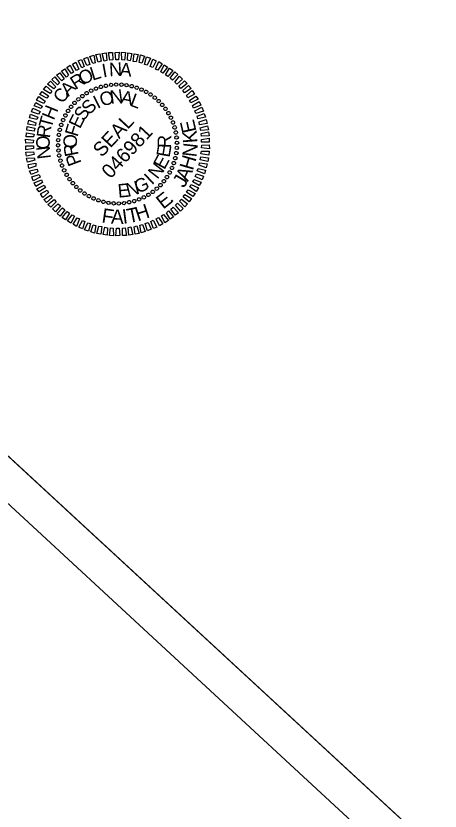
# Model space of a CAD drawing. Extents: x 1768274 to 1769121, y 999922 to 1000687.
# Drawn here: x 1769004.6 to 1769037.2, y 1000252.8 to 1000314 of the extents above; entities that cross this region are included whole.
import ezdxf

# ---------------------------------------------------------------- set-up
doc = ezdxf.new("R2010")
doc.units = 0
for name, color, linetype in [('E_NCDOT_Terrain_Model_Contour_Major', 7, 'Continuous'), ('E_NCDOT_Terrain_Model_Spot_Elevation', 7, 'Continuous'), ('E_NCDOT_Terrain_Model_Triangle_Vertices', 7, 'Continuous'), ('E_NCDOT_Terrain_Model_Void', 7, 'Continuous')]:
    doc.layers.add(name, color=color, linetype=linetype)

msp = doc.modelspace()

# ---------------------------------------------------------------- linework, layer by layer
at = {"layer": 'E_NCDOT_Terrain_Model_Contour_Major'}
msp.add_line((1769116.231, 1000172.715), (1768961.29, 1000315.942), dxfattribs=at)
at = {"layer": 'E_NCDOT_Terrain_Model_Spot_Elevation'}
msp.add_lwpolyline([(1768729.032, 1000071.305), (1768959.819, 1000320.98), (1769121.372, 1000171.648), (1768890.585, 999921.973)], close=True, dxfattribs=at)
at = {"layer": 'E_NCDOT_Terrain_Model_Triangle_Vertices'}
msp.add_line((1769121.372, 1000171.648), (1768959.819, 1000320.98), dxfattribs=at)
at = {"layer": 'E_NCDOT_Terrain_Model_Void'}
for p, q in [((1769010.398, 1000308.223), (1769010.398, 1000308.223)), ((1769010.766, 1000308.38), (1769010.766, 1000308.38)), ((1769011.141, 1000308.517), (1769011.141, 1000308.517)), ((1769011.531, 1000308.603), (1769011.531, 1000308.603)), ((1769011.928, 1000308.67), (1769011.928, 1000308.67)), ((1769012.32, 1000308.692), (1769012.32, 1000308.692)), ((1769012.727, 1000308.689), (1769012.727, 1000308.689)), ((1769013.116, 1000308.64), (1769013.116, 1000308.64)), ((1769013.512, 1000308.558), (1769013.512, 1000308.558)), ((1769013.897, 1000308.451), (1769013.897, 1000308.451)), ((1769014.264, 1000308.311), (1769014.264, 1000308.311)), ((1769009.724, 1000307.803), (1769009.724, 1000307.803)), ((1769010.044, 1000308.029), (1769010.044, 1000308.029)), ((1769014.619, 1000308.131), (1769014.619, 1000308.131)), ((1769014.963, 1000307.913), (1769014.963, 1000307.913)), ((1769015.288, 1000307.687), (1769015.288, 1000307.687)), ((1769008.853, 1000306.982), (1769008.853, 1000306.982)), ((1769009.119, 1000307.283), (1769009.119, 1000307.283)), ((1769009.411, 1000307.559), (1769009.411, 1000307.559)), ((1769015.588, 1000307.421), (1769015.588, 1000307.421)), ((1769015.864, 1000307.129), (1769015.864, 1000307.129)), ((1769008.628, 1000306.657), (1769008.628, 1000306.657)), ((1769016.109, 1000306.816), (1769016.109, 1000306.816)), ((1769016.334, 1000306.496), (1769016.334, 1000306.496)), ((1769008.229, 1000305.958), (1769008.229, 1000305.958)), ((1769008.409, 1000306.313), (1769008.409, 1000306.313)), ((1769016.529, 1000306.143), (1769016.529, 1000306.143)), ((1769016.685, 1000305.775), (1769016.685, 1000305.775)), ((1769007.982, 1000305.207), (1769007.982, 1000305.207)), ((1769008.089, 1000305.591), (1769008.089, 1000305.591)), ((1769016.822, 1000305.4), (1769016.822, 1000305.4)), ((1769007.901, 1000304.81), (1769007.901, 1000304.81)), ((1769016.909, 1000305.009), (1769016.909, 1000305.009)), ((1769016.976, 1000304.612), (1769016.976, 1000304.612)), ((1769007.848, 1000304.015), (1769007.848, 1000304.015)), ((1769007.851, 1000304.421), (1769007.851, 1000304.421)), ((1769012.423, 1000304.117), (1769012.423, 1000304.117)), ((1769016.998, 1000304.22), (1769016.998, 1000304.22)), ((1769007.87, 1000303.622), (1769007.87, 1000303.622)), ((1769016.945, 1000303.424), (1769016.945, 1000303.424)), ((1769016.994, 1000303.813), (1769016.994, 1000303.813)), ((1769007.937, 1000303.225), (1769007.937, 1000303.225)), ((1769008.023, 1000302.835), (1769008.023, 1000302.835)), ((1769016.864, 1000303.028), (1769016.864, 1000303.028)), ((1769008.161, 1000302.46), (1769008.161, 1000302.46)), ((1769008.317, 1000302.092), (1769008.317, 1000302.092)), ((1769016.616, 1000302.276), (1769016.616, 1000302.276)), ((1769016.757, 1000302.643), (1769016.757, 1000302.643)), ((1769008.511, 1000301.739), (1769008.511, 1000301.739)), ((1769016.218, 1000301.577), (1769016.218, 1000301.577)), ((1769016.437, 1000301.921), (1769016.437, 1000301.921)), ((1769008.737, 1000301.419), (1769008.737, 1000301.419)), ((1769008.981, 1000301.106), (1769008.981, 1000301.106)), ((1769015.727, 1000300.952), (1769015.727, 1000300.952)), ((1769015.992, 1000301.252), (1769015.992, 1000301.252)), ((1769009.257, 1000300.813), (1769009.257, 1000300.813)), ((1769009.558, 1000300.548), (1769009.558, 1000300.548)), ((1769009.883, 1000300.322), (1769009.883, 1000300.322)), ((1769015.122, 1000300.431), (1769015.122, 1000300.431)), ((1769015.434, 1000300.676), (1769015.434, 1000300.676)), ((1769010.227, 1000300.103), (1769010.227, 1000300.103)), ((1769010.582, 1000299.924), (1769010.582, 1000299.924)), ((1769010.949, 1000299.784), (1769010.949, 1000299.784)), ((1769011.333, 1000299.676), (1769011.333, 1000299.676)), ((1769013.705, 1000299.718), (1769013.705, 1000299.718)), ((1769014.08, 1000299.855), (1769014.08, 1000299.855)), ((1769014.448, 1000300.011), (1769014.448, 1000300.011)), ((1769014.802, 1000300.206), (1769014.802, 1000300.206)), ((1769011.73, 1000299.595), (1769011.73, 1000299.595)), ((1769012.119, 1000299.546), (1769012.119, 1000299.546)), ((1769012.525, 1000299.542), (1769012.525, 1000299.542)), ((1769012.918, 1000299.564), (1769012.918, 1000299.564)), ((1769013.315, 1000299.632), (1769013.315, 1000299.632))]:
    msp.add_line(p, q, dxfattribs=at)
for points in [[(1769010.077, 1000310.145), (1769009.837, 1000310.678), (1769010.122, 1000310.798), (1769010.287, 1000310.225)], [(1769010.515, 1000310.311), (1769010.301, 1000310.844), (1769010.6, 1000310.94), (1769010.713, 1000310.364)], [(1769010.937, 1000310.405), (1769010.766, 1000310.998), (1769011.067, 1000311.042), (1769011.154, 1000310.478)], [(1769011.392, 1000310.494), (1769011.253, 1000311.082), (1769011.561, 1000311.119), (1769011.603, 1000310.534)], [(1769011.834, 1000310.556), (1769011.74, 1000311.152), (1769012.049, 1000311.164), (1769012.052, 1000310.591)], [(1769012.291, 1000310.581), (1769012.243, 1000311.159), (1769012.552, 1000311.171), (1769012.491, 1000310.582)], [(1769012.749, 1000310.592), (1769012.732, 1000311.178), (1769013.043, 1000311.152), (1769012.969, 1000310.562)], [(1769013.195, 1000310.552), (1769013.217, 1000311.139), (1769013.529, 1000311.087), (1769013.397, 1000310.514)], [(1769013.631, 1000310.472), (1769013.704, 1000311.062), (1769014.022, 1000311.003), (1769013.851, 1000310.442)], [(1769014.086, 1000310.374), (1769014.198, 1000310.965), (1769014.486, 1000310.86), (1769014.287, 1000310.337)], [(1769014.497, 1000310.242), (1769014.662, 1000310.822), (1769014.956, 1000310.711), (1769014.706, 1000310.173)], [(1769014.923, 1000310.071), (1769015.127, 1000310.64), (1769015.402, 1000310.522), (1769015.126, 1000310.008)], [(1769008.889, 1000309.531), (1769008.516, 1000310), (1769008.779, 1000310.178), (1769009.052, 1000309.641)], [(1769009.273, 1000309.772), (1769008.951, 1000310.256), (1769009.209, 1000310.401), (1769009.449, 1000309.869)], [(1769009.671, 1000309.962), (1769009.392, 1000310.505), (1769009.646, 1000310.618), (1769009.861, 1000310.072)], [(1769015.343, 1000309.882), (1769015.585, 1000310.452), (1769015.843, 1000310.288), (1769015.527, 1000309.799)], [(1769015.739, 1000309.665), (1769016.001, 1000310.204), (1769016.266, 1000310.034), (1769015.917, 1000309.575)], [(1769008.149, 1000308.986), (1769007.739, 1000309.415), (1769007.983, 1000309.599), (1769008.324, 1000309.122)], [(1769008.5, 1000309.258), (1769008.127, 1000309.714), (1769008.365, 1000309.904), (1769008.668, 1000309.4)], [(1769016.116, 1000309.428), (1769016.424, 1000309.95), (1769016.67, 1000309.76), (1769016.301, 1000309.307)], [(1769016.474, 1000309.171), (1769016.823, 1000309.656), (1769017.063, 1000309.459), (1769016.647, 1000309.036)], [(1769007.516, 1000308.355), (1769007.05, 1000308.724), (1769007.261, 1000308.938), (1769007.671, 1000308.509)], [(1769007.82, 1000308.67), (1769007.385, 1000309.072), (1769007.596, 1000309.287), (1769007.975, 1000308.824)], [(1769016.815, 1000308.869), (1769017.197, 1000309.322), (1769017.425, 1000309.112), (1769016.976, 1000308.72)], [(1769017.143, 1000308.553), (1769017.559, 1000308.975), (1769017.767, 1000308.758), (1769017.292, 1000308.391)], [(1769007.24, 1000307.989), (1769006.744, 1000308.312), (1769006.927, 1000308.564), (1769007.369, 1000308.169)], [(1769017.434, 1000308.222), (1769017.87, 1000308.614), (1769018.073, 1000308.377), (1769017.563, 1000308.041)], [(1769017.726, 1000307.853), (1769018.163, 1000308.219), (1769018.347, 1000307.962), (1769017.817, 1000307.67)], [(1769006.76, 1000307.242), (1769006.209, 1000307.491), (1769006.372, 1000307.762), (1769006.857, 1000307.413)], [(1769006.984, 1000307.631), (1769006.456, 1000307.92), (1769006.64, 1000308.159), (1769007.112, 1000307.81)], [(1769017.966, 1000307.47), (1769018.437, 1000307.804), (1769018.614, 1000307.553), (1769018.057, 1000307.286)], [(1769006.55, 1000306.84), (1769006.006, 1000307.057), (1769006.138, 1000307.321), (1769006.633, 1000307.024)], [(1769018.195, 1000307.072), (1769018.699, 1000307.376), (1769018.826, 1000307.097), (1769018.267, 1000306.869)], [(1769006.223, 1000305.989), (1769005.65, 1000306.121), (1769005.748, 1000306.415), (1769006.298, 1000306.192)], [(1769006.354, 1000306.413), (1769005.805, 1000306.598), (1769005.911, 1000306.873), (1769006.469, 1000306.618)], [(1769018.366, 1000306.666), (1769018.903, 1000306.939), (1769019.018, 1000306.647), (1769018.451, 1000306.463)], [(1769018.55, 1000306.248), (1769019.07, 1000306.475), (1769019.184, 1000306.182), (1769018.603, 1000306.05)], [(1769006.117, 1000305.553), (1769005.527, 1000305.639), (1769005.612, 1000305.946), (1769006.154, 1000305.754)], [(1769018.689, 1000305.821), (1769019.236, 1000306.01), (1769019.3, 1000305.703), (1769018.71, 1000305.603)], [(1769006.012, 1000305.104), (1769005.442, 1000305.171), (1769005.476, 1000305.463), (1769006.068, 1000305.325)], [(1769018.771, 1000305.373), (1769019.333, 1000305.524), (1769019.409, 1000305.217), (1769018.818, 1000305.168)], [(1769005.978, 1000304.664), (1769005.391, 1000304.673), (1769005.417, 1000304.983), (1769006.009, 1000304.871)], [(1769018.84, 1000304.937), (1769019.422, 1000305.044), (1769019.46, 1000304.736), (1769018.874, 1000304.732)], [(1769018.878, 1000304.468), (1769019.467, 1000304.555), (1769019.467, 1000304.246), (1769018.886, 1000304.262)], [(1769005.938, 1000304.204), (1769005.371, 1000304.182), (1769005.359, 1000304.491), (1769005.962, 1000304.418)], [(1769005.968, 1000303.767), (1769005.378, 1000303.679), (1769005.379, 1000303.989), (1769005.96, 1000303.973)], [(1769018.908, 1000304.03), (1769019.474, 1000304.053), (1769019.486, 1000303.744), (1769018.884, 1000303.817)], [(1769006.006, 1000303.298), (1769005.423, 1000303.191), (1769005.385, 1000303.499), (1769005.972, 1000303.503)], [(1769018.868, 1000303.571), (1769019.455, 1000303.562), (1769019.428, 1000303.251), (1769018.837, 1000303.363)], [(1769006.075, 1000302.862), (1769005.513, 1000302.711), (1769005.437, 1000303.017), (1769006.028, 1000303.066)], [(1769018.833, 1000303.131), (1769019.404, 1000303.063), (1769019.37, 1000302.772), (1769018.778, 1000302.91)], [(1769006.157, 1000302.413), (1769005.61, 1000302.224), (1769005.546, 1000302.531), (1769006.135, 1000302.632)], [(1769006.296, 1000301.987), (1769005.776, 1000301.76), (1769005.661, 1000302.052), (1769006.243, 1000302.185)], [(1769018.623, 1000302.246), (1769019.196, 1000302.113), (1769019.098, 1000301.819), (1769018.547, 1000302.043)], [(1769018.729, 1000302.682), (1769019.319, 1000302.596), (1769019.234, 1000302.289), (1769018.691, 1000302.481)], [(1769006.48, 1000301.568), (1769005.943, 1000301.296), (1769005.828, 1000301.588), (1769006.395, 1000301.771)], [(1769018.491, 1000301.821), (1769019.04, 1000301.637), (1769018.935, 1000301.362), (1769018.377, 1000301.617)], [(1769006.651, 1000301.162), (1769006.147, 1000300.859), (1769006.02, 1000301.138), (1769006.578, 1000301.366)], [(1769006.879, 1000300.765), (1769006.409, 1000300.431), (1769006.231, 1000300.682), (1769006.788, 1000300.949)], [(1769018.086, 1000300.993), (1769018.637, 1000300.744), (1769018.474, 1000300.473), (1769017.989, 1000300.821)], [(1769018.295, 1000301.394), (1769018.839, 1000301.177), (1769018.708, 1000300.914), (1769018.212, 1000301.211)], [(1769007.12, 1000300.381), (1769006.683, 1000300.016), (1769006.499, 1000300.273), (1769007.029, 1000300.565)], [(1769017.605, 1000300.245), (1769018.102, 1000299.923), (1769017.918, 1000299.671), (1769017.477, 1000300.066)], [(1769017.862, 1000300.604), (1769018.389, 1000300.315), (1769018.205, 1000300.075), (1769017.734, 1000300.424)], [(1769007.412, 1000300.012), (1769006.976, 1000299.621), (1769006.773, 1000299.858), (1769007.282, 1000300.194)], [(1769007.702, 1000299.682), (1769007.287, 1000299.259), (1769007.078, 1000299.477), (1769007.554, 1000299.844)], [(1769017.33, 1000299.88), (1769017.796, 1000299.511), (1769017.585, 1000299.296), (1769017.174, 1000299.725)], [(1769008.031, 1000299.366), (1769007.649, 1000298.912), (1769007.421, 1000299.123), (1769007.87, 1000299.514)], [(1769008.372, 1000299.063), (1769008.023, 1000298.579), (1769007.783, 1000298.776), (1769008.199, 1000299.198)], [(1769016.697, 1000299.249), (1769017.107, 1000298.82), (1769016.863, 1000298.636), (1769016.521, 1000299.113)], [(1769017.026, 1000299.565), (1769017.461, 1000299.162), (1769017.25, 1000298.948), (1769016.871, 1000299.41)], [(1769008.73, 1000298.806), (1769008.421, 1000298.285), (1769008.175, 1000298.475), (1769008.545, 1000298.928)], [(1769009.107, 1000298.57), (1769008.844, 1000298.03), (1769008.58, 1000298.201), (1769008.929, 1000298.659)], [(1769009.502, 1000298.353), (1769009.26, 1000297.782), (1769009.002, 1000297.946), (1769009.318, 1000298.436)], [(1769015.573, 1000298.463), (1769015.895, 1000297.979), (1769015.637, 1000297.833), (1769015.396, 1000298.365)], [(1769015.957, 1000298.704), (1769016.33, 1000298.234), (1769016.066, 1000298.056), (1769015.794, 1000298.594)], [(1769016.346, 1000298.977), (1769016.719, 1000298.521), (1769016.481, 1000298.331), (1769016.178, 1000298.835)], [(1769009.922, 1000298.163), (1769009.719, 1000297.594), (1769009.444, 1000297.712), (1769009.72, 1000298.226)], [(1769010.348, 1000297.993), (1769010.184, 1000297.412), (1769009.89, 1000297.523), (1769010.139, 1000298.062)], [(1769010.76, 1000297.861), (1769010.648, 1000297.269), (1769010.36, 1000297.374), (1769010.558, 1000297.898)], [(1769013.908, 1000297.83), (1769014.08, 1000297.237), (1769013.779, 1000297.193), (1769013.692, 1000297.757)], [(1769014.33, 1000297.924), (1769014.545, 1000297.39), (1769014.245, 1000297.295), (1769014.132, 1000297.871)], [(1769014.769, 1000298.089), (1769015.009, 1000297.557), (1769014.723, 1000297.436), (1769014.559, 1000298.01)], [(1769015.174, 1000298.273), (1769015.454, 1000297.729), (1769015.2, 1000297.616), (1769014.985, 1000298.162)], [(1769011.215, 1000297.763), (1769011.142, 1000297.173), (1769010.823, 1000297.231), (1769010.995, 1000297.793)], [(1769011.65, 1000297.683), (1769011.628, 1000297.095), (1769011.317, 1000297.147), (1769011.449, 1000297.72)], [(1769012.097, 1000297.642), (1769012.114, 1000297.056), (1769011.803, 1000297.083), (1769011.877, 1000297.672)], [(1769012.554, 1000297.654), (1769012.603, 1000297.075), (1769012.294, 1000297.063), (1769012.355, 1000297.653)], [(1769013.011, 1000297.678), (1769013.106, 1000297.082), (1769012.797, 1000297.07), (1769012.793, 1000297.644)], [(1769013.454, 1000297.741), (1769013.593, 1000297.153), (1769013.285, 1000297.115), (1769013.243, 1000297.7)]]:
    msp.add_lwpolyline(points, close=True, dxfattribs=at)
for centre, major_axis in [((1769012.323, 1000308.688), (-0.003, 0.131)), ((1769012.722, 1000308.679), (0.009, 0.131)), ((1769010.401, 1000308.217), (-0.058, 0.118)), ((1769010.766, 1000308.378), (-0.048, 0.122)), ((1769011.144, 1000308.506), (-0.037, 0.126)), ((1769011.531, 1000308.601), (-0.026, 0.129)), ((1769011.925, 1000308.661), (-0.014, 0.13)), ((1769013.118, 1000308.635), (0.02, 0.13)), ((1769013.509, 1000308.558), (0.031, 0.127)), ((1769013.892, 1000308.446), (0.042, 0.124)), ((1769014.264, 1000308.301), (0.053, 0.12)), ((1769014.622, 1000308.125), (0.063, 0.115)), ((1769009.409, 1000307.554), (-0.0865, 0.0987)), ((1769009.72, 1000307.804), (-0.078, 0.106)), ((1769010.051, 1000308.025), (-0.068, 0.112)), ((1769014.962, 1000307.918), (0.073, 0.109)), ((1769015.284, 1000307.682), (0.082, 0.102)), ((1769008.858, 1000306.979), (-0.102, 0.082)), ((1769009.121, 1000307.278), (-0.0948, 0.0907)), ((1769015.584, 1000307.42), (0.0907, 0.0948)), ((1769015.86, 1000307.131), (0.0987, 0.0865)), ((1769008.415, 1000306.316), (-0.115, 0.063)), ((1769008.622, 1000306.657), (-0.109, 0.073)), ((1769016.109, 1000306.82), (0.106, 0.078)), ((1769016.331, 1000306.489), (0.112, 0.068)), ((1769008.239, 1000305.958), (-0.12, 0.053)), ((1769016.523, 1000306.139), (0.118, 0.058)), ((1769016.683, 1000305.774), (0.122, 0.048)), ((1769007.983, 1000305.204), (-0.127, 0.031)), ((1769008.094, 1000305.587), (-0.124, 0.042)), ((1769016.812, 1000305.397), (0.126, 0.037)), ((1769016.906, 1000305.009), (0.129, 0.026)), ((1769007.861, 1000304.416), (-0.131, 0.009)), ((1769007.905, 1000304.813), (-0.13, 0.02)), ((1769016.967, 1000304.615), (0.13, 0.014)), ((1769007.853, 1000304.017), (-0.131, -0.003)), ((1769016.984, 1000303.818), (0.131, -0.009)), ((1769016.993, 1000304.217), (0.131, 0.003)), ((1769007.879, 1000303.62), (-0.13, -0.014)), ((1769007.939, 1000303.225), (-0.129, -0.026)), ((1769016.941, 1000303.422), (0.13, -0.02)), ((1769008.034, 1000302.838), (-0.126, -0.037)), ((1769016.752, 1000302.648), (0.124, -0.042)), ((1769016.863, 1000303.031), (0.127, -0.031)), ((1769008.162, 1000302.46), (-0.122, -0.048)), ((1769008.323, 1000302.095), (-0.118, -0.058)), ((1769016.607, 1000302.276), (0.12, -0.053)), ((1769008.515, 1000301.746), (-0.112, -0.068)), ((1769008.736, 1000301.414), (-0.106, -0.078)), ((1769016.224, 1000301.578), (0.109, -0.073)), ((1769016.431, 1000301.919), (0.115, -0.063)), ((1769008.986, 1000301.103), (-0.0987, -0.0865)), ((1769009.262, 1000300.815), (-0.0907, -0.0948)), ((1769015.725, 1000300.956), (0.0948, -0.0907)), ((1769015.988, 1000301.256), (0.102, -0.082)), ((1769009.562, 1000300.552), (-0.082, -0.102)), ((1769009.883, 1000300.316), (-0.073, -0.109)), ((1769010.224, 1000300.109), (-0.063, -0.115)), ((1769014.794, 1000300.209), (0.068, -0.112)), ((1769015.126, 1000300.431), (0.078, -0.106)), ((1769015.437, 1000300.68), (0.0865, -0.0987)), ((1769010.582, 1000299.933), (-0.053, -0.12)), ((1769010.954, 1000299.789), (-0.042, -0.124)), ((1769011.336, 1000299.677), (-0.031, -0.127)), ((1769011.728, 1000299.599), (-0.02, -0.13)), ((1769012.124, 1000299.556), (-0.009, -0.131)), ((1769012.523, 1000299.547), (0.003, -0.131)), ((1769012.921, 1000299.573), (0.014, -0.13)), ((1769013.315, 1000299.634), (0.026, -0.129)), ((1769013.702, 1000299.729), (0.037, -0.126)), ((1769014.08, 1000299.857), (0.048, -0.122)), ((1769014.445, 1000300.017), (0.058, -0.118))]:
    msp.add_ellipse(centre, major_axis=major_axis, ratio=0.999708, dxfattribs=at)

# ---------------------------------------------------------------- texts
for s, height, rotation, p in [('L', 1.037, 17.4721, (1769010.503, 1000308.982)), ('I', 1.038, 10.27137, (1769011.326, 1000309.227)), ('N', 1.039, 3.07014, (1769011.799, 1000309.323)), ('A', 1.038, 355.86838, (1769012.559, 1000309.353)), ('R', 1.031, 31.87232, (1769009.196, 1000308.266)), ('O', 1.034, 24.67239, (1769009.711, 1000308.622)), ('A', 1.028, 46.27155, (1769008.65, 1000307.729)), ('C', 1.028, 53.4711, (1769008.201, 1000307.163)), ('N', 1.039, 7.72784, (1769011.909, 1000307.186)), ('I', 1.033, 26.44083, (1769010.886, 1000306.804)), ('O', 1.037, 17.08471, (1769011.227, 1000306.985)), ('A', 1.037, 349.01149, (1769012.609, 1000307.246)), ('L', 1.033, 339.65208, (1769013.312, 1000307.08)), ('H', 1.033, 67.8707, (1769007.529, 1000305.898)), ('S', 1.028, 54.50684, (1769009.821, 1000305.827)), ('S', 1.028, 45.15163, (1769010.26, 1000306.315)), ('E', 1.031, 63.86229, (1769009.535, 1000305.236)), ('T', 1.036, 75.071, (1769007.348, 1000305.259)), ('SEAL', 1.0933, 47.25123, (1769011.221, 1000303.045)), ('E', 1.103, 102.74425, (1769018.497, 1000305.105)), ('R', 1.038, 82.27173, (1769007.221, 1000304.532)), ('F', 1.035, 73.21826, (1769009.34, 1000304.622)), ('046981', 1.0933, 47.25123, (1769011.89, 1000301.39)), ('K', 1.105, 94.46033, (1769018.576, 1000304.22)), ('O', 1.039, 89.47297, (1769007.21, 1000303.687)), ('O', 1.039, 91.93247, (1769009.326, 1000303.815)), ('R', 1.039, 89.73264, (1769016.543, 1000303.808)), ('R', 1.038, 101.29088, (1769009.438, 1000303.278)), ('E', 1.038, 80.37532, (1769016.418, 1000303.043)), ('N', 1.105, 83.7345, (1769018.488, 1000303.073)), ('N', 1.039, 96.67473, (1769007.313, 1000303.02)), ('E', 1.031, 61.66299, (1769016.024, 1000302.092)), ('P', 1.035, 110.65012, (1769009.668, 1000302.668)), ('H', 1.102, 73.75051, (1769018.215, 1000302.037)), ('N', 1.028, 52.30762, (1769015.492, 1000301.355)), ('A', 1.098, 64.91021, (1769017.826, 1000301.172)), ('G', 1.034, 24.24147, (1769013.992, 1000300.284)), ('I', 1.028, 42.95243, (1769015.057, 1000300.925)), ('J', 1.096, 59.65239, (1769017.534, 1000300.689)), ('E', 1.039, 5.52812, (1769012.489, 1000299.986)), ('N', 1.037, 14.88518, (1769013.221, 1000300.053)), ('E', 1.095, 38.30892, (1769015.935, 1000299.064)), ('.', 1.093, 45.41825, (1769016.534, 1000299.538)), ('F', 1.103, 351.66547, (1769011.16, 1000298.094)), ('A', 1.105, 358.68208, (1769011.906, 1000297.985)), ('I', 1.105, 7.52239, (1769012.854, 1000297.978)), ('T', 1.105, 11.32434, (1769013.26, 1000298.02)), ('H', 1.103, 18.12458, (1769013.976, 1000298.163))]:
    msp.add_text(s, height=height, rotation=rotation, dxfattribs=at).set_placement(p)

doc.saveas('drawing.dxf')
